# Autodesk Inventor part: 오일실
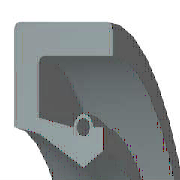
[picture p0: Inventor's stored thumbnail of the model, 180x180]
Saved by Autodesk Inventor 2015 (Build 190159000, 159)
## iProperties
Created: 2009-02
Part Number: 오일실
Material: Rubber
Description: 오일-실
Document SubType Name: Modeling
Standard: KS B 2804
Designer: KYOUNG IL JANG
Standards Organization: KS
Language: ko-KR
Size Designation: S - 18 30 8
Categories: <MemberInstance><Categories><Category DisplayName="샤프트 부품" InternalName="7f7aeb1f-a693-4053-b835-cee3144e0d98" Mnemonic="SHFT"><Category DisplayName="실링" Intern
Density: 0.93 g/cm^3
Appearance: Rubber - Black - Version 1.1
Company: 한국ATC센터
IsCustomPart: 1
Author: KYOUNG IL JANG
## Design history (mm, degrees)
revolve "본체" stored, may be unused: angle "d17" = 90 deg
revolve "스프링1" stored, may be unused: angle "d18" = 90 deg
body "Solid1"
sketch "스케치1"
  geometry: L1 (0, 15)-(8, 15); L2 (8, 15)-(8, 13.75); L3 (8, 13.75)-(1.75, 13.75); L4 (0, 15)-(0, 11.1); L5 (0, 11.1)-(1.75, 10.75); L6 (1.75, 10.75)-(4.9, 9); L7 (4.9, 9)-(0, 9); L8 (6.3, 9.875)-(6.3, 11.1); L9 (0, 0)-(9.586, 0) reference; L10 (4.9, 9)-(6.3, 9.875); L11 (0, 18)-(0, -3) reference; L12 (-1.917, 0)-(11.503, 0) reference; L13 (4.2, 11.1)-(1.75, 11.59); L14 (1.75, 11.59)-(1.75, 13.75); L15 (6.3, 11.1)-(5.6, 11.1); C1 r 0.455 at (4.9, 11.1); A1 r 0.7 centre (4.9, 11.1) between (5.6, 11.1) and (4.2, 11.1)
  constraints: 26 end point, 5 horizontal alignment, 4 perpendicular, 2 centre point, 2 collinear, 2 horizontal, 2 parallel, 2 point on circle, 2 point on line, 2 vertical alignment, 1 coincident
  dimensions: "d0" = 30 diameter of L1 L9 (= SD2); "d1" = 19.75 diameter of L8.start L9 (= ABDM); "d2" = 1.25 distance of L1.end L2.end (computed from SD); "d3" = 0.91 diameter of C1 (= SPDI); "d4" = 1.4 diameter of A1 (= SPDA); "d5" = 18 diameter of L6.end L9 (= NND); "d6" = 21.5 diameter of L5.end L9 (= TKDM); "d7" = 22.2 diameter of L4.end L9 (= HLDM); "d8" = 4.9 distance from line of C1.centre L4 (= SPDST); "d9" = 6.3 distance between parallel lines of L8 L4 (= SDI); "d10" = 8 distance between parallel lines of L2 L4 (= SWDT); "d12" = 1.75 distance between parallel lines of L14 L4 (= SD)
fillet "모깎기1" dims "d11" = 0.3 (= RR)
other parameters: "SD2" = 30 [user parameter; used in 1 equation term], "SWDT" = 8 [user parameter; used in 1 equation term], "RR" = 0.3 [user parameter; used in 1 equation term], "SD" = 1.75 [user parameter; used in 2 equation terms], "NND" = 18 [user parameter; used in 1 equation term], "SPDA" = 1.4 [user parameter; used in 1 equation term], "SPDI" = 0.91 [user parameter; used in 1 equation term], "TKDM" = 21.5 [user parameter; used in 1 equation term], "HLDM" = 22.2 [user parameter; used in 1 equation term], "ABDM" = 19.75 [user parameter; used in 1 equation term], "SDI" = 6.3 [user parameter; used in 1 equation term], "SPDST" = 4.9 [user parameter; used in 1 equation term], "d13" = 0, "d14" = 0, "d15" = 0, "LAB" = 0.35 [user parameter]
